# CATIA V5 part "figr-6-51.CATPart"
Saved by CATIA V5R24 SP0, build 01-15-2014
Part number: Part1
Bounding box of the stored display mesh (mm): x -54.76 to 54.76, y -32.885 to 32.885, z 0 to 59
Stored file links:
  D:\KAVITA\CATIA V5-6R2014 Project_ Kavita\CATIA V5-6R2014_partfiles\Partfiles\c06_catia_v5-6r2014_prt\figr-6-51.CATPart
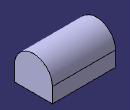
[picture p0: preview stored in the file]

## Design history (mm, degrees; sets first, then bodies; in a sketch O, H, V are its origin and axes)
Body1 (main body)
  Sketch1 on xy-plane, origin (0, 0, 0), H (1, 0, 0), V (0, 1, 0)
    line L1 (-54.7599, 32.8853) -> (54.7599, 32.8853)
    line L2 (54.7599, 32.8853) -> (54.7599, -32.8853)
    line L3 (54.7599, -32.8853) -> (-54.7599, -32.8853)
    line L4 (-54.7599, -32.8853) -> (-54.7599, 32.8853)
    axis line L5 (54.7599, -32.8853) -> (-54.7599, 32.8853)
    horizontal: L1 H, L3 H
    vertical: L2 V, L4 V
    midpoint: O L5
  Pad1: profile Sketch1, direction (0, 0, 1), length 59
  TritangentFillet1: Face1 face of Pad1, Face2 face of Pad1, RemoveFace face of Pad1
